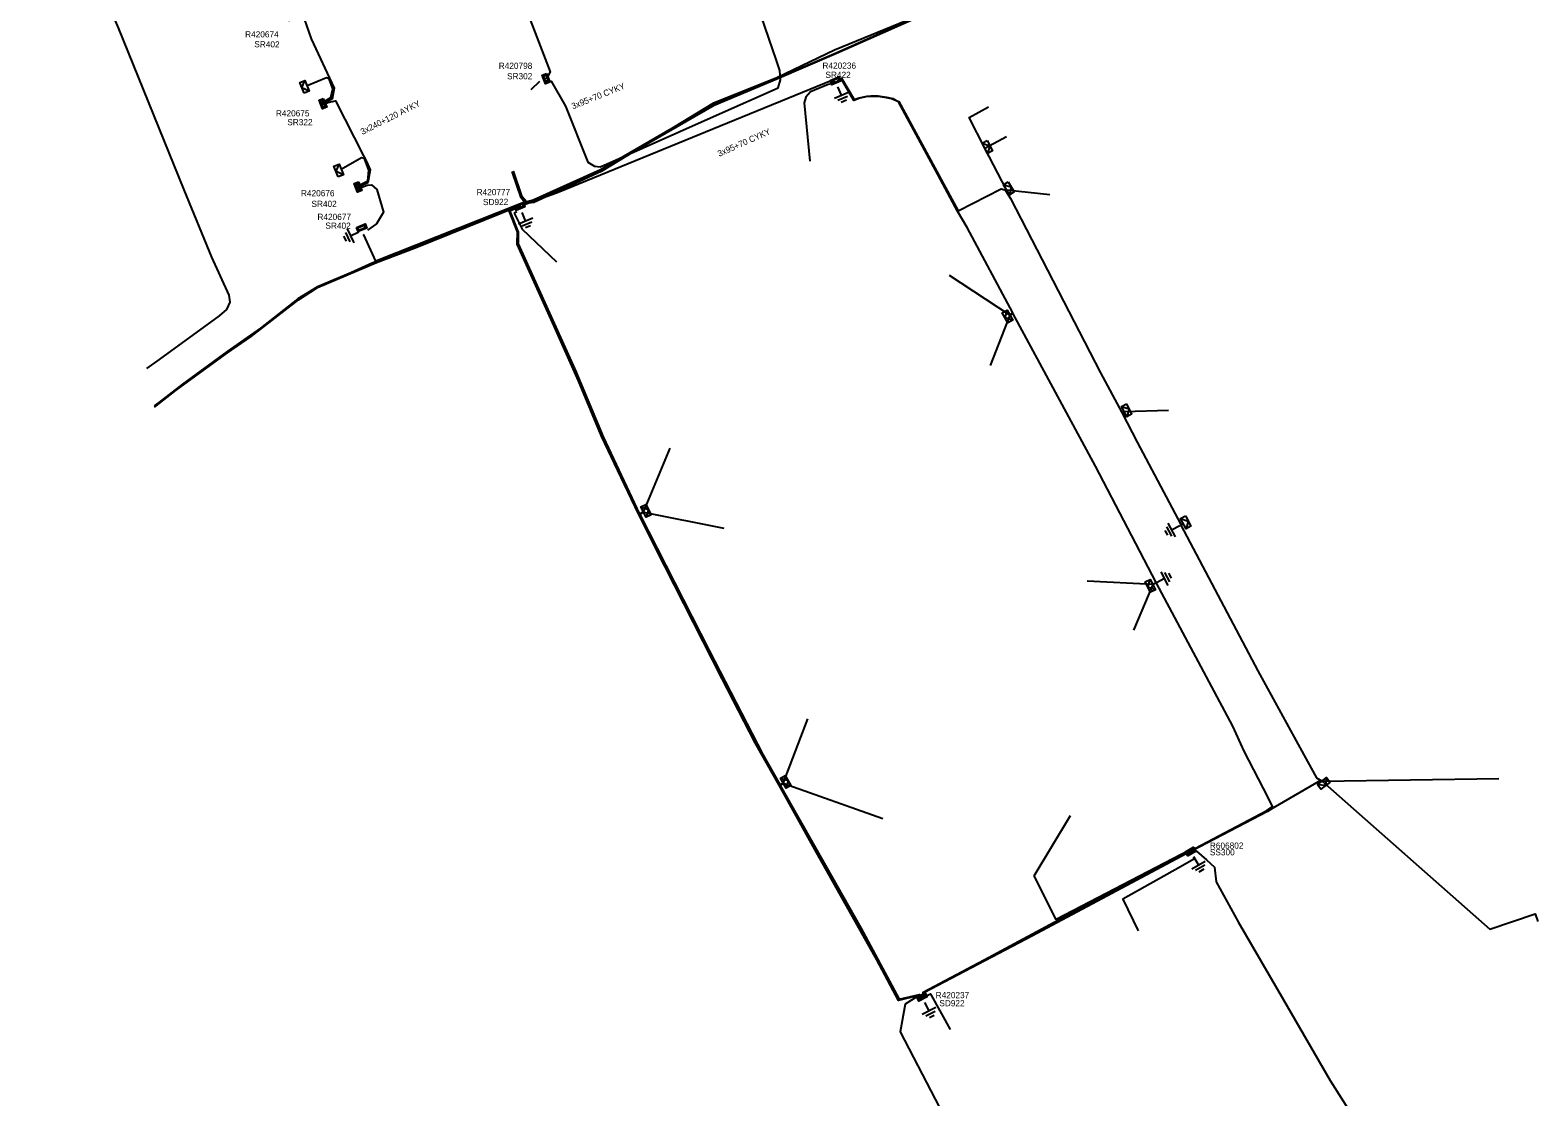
# Model space of a CAD drawing. Extents: x -540028 to -538776, y -1157064 to -1155670.
# Drawn here: x -539936.3 to -539692.4, y -1156587.3 to -1156414.7 of the extents above; entities that cross this region are included whole.
import ezdxf

# ---------------------------------------------------------------- set-up
doc = ezdxf.new("R2010")
doc.units = 0
for name, color, linetype in [('Vrstva 15', 7, 'Continuous'), ('Vrstva 2', 7, 'Continuous'), ('Vrstva 28', 7, 'Continuous'), ('Vrstva 29', 7, 'Continuous'), ('Vrstva 30', 7, 'Continuous'), ('Vrstva 31', 7, 'Continuous'), ('Vrstva 5', 7, 'Continuous'), ('Vrstva 52', 7, 'Continuous'), ('Vrstva 59', 7, 'Continuous'), ('Vrstva 6', 7, 'Continuous'), ('Vrstva 9', 7, 'Continuous')]:
    doc.layers.add(name, color=color, linetype=linetype)

# ---------------------------------------------------------------- blocks, each defined once
blk = doc.blocks.new('132')
at = {"layer": 'Vrstva 2'}
for points in [[(-1.5, 1.5), (1.5, 1.5), (1.5, 0), (-1.5, 0)], [(-1.1, 1.2), (1.1, 1.2), (1.1, 0.3), (-1.1, 0.3)]]:
    blk.add_lwpolyline(points, close=True, dxfattribs=at)
blk = doc.blocks.new('23')
at = {"layer": 'Vrstva 2'}
blk.add_lwpolyline([(1.875, -1.8), (-1.875, -1.8), (-1.875, 0), (1.875, 0)], close=True, dxfattribs=at)
blk.add_lwpolyline([(1.875, 0), (0, -1.8), (-1.875, 0)], dxfattribs=at)
blk = doc.blocks.new('11')
at = {"layer": 'Vrstva 2'}
for p, q in [((-2.5, -4.3), (2.5, -4.3)), ((0, -4.3), (0, -1.3)), ((-1.7, -5.3), (1.7, -5.3)), ((-0.9, -6.3), (0.9, -6.3))]:
    blk.add_line(p, q, dxfattribs=at)

msp = doc.modelspace()

# ---------------------------------------------------------------- linework, layer by layer
at = {"layer": 'Vrstva 5'}
for points in [[(-539936.27, -1156379.01), (-539935.17, -1156382.16), (-539934, -1156386.11), (-539929.5, -1156397.08), (-539922.06, -1156414.34), (-539911.42, -1156440.51), (-539906.94, -1156451.42), (-539904.12, -1156457.59), (-539903.96, -1156458.69), (-539904.52, -1156459.9), (-539905.72, -1156460.91), (-539915.38, -1156467.98), (-539917.46, -1156469.44)], [(-539859.58, -1156406.32), (-539858.22, -1156406.28), (-539857.01, -1156408.79), (-539852.18, -1156421.45), (-539852.7, -1156422.48), (-539853.18, -1156422.63)], [(-539853.12, -1156422.78), (-539851.98, -1156422.96), (-539849.68, -1156426.99), (-539846.07, -1156436.04), (-539845, -1156436.69), (-539844.1, -1156436.81), (-539843.07, -1156436.4), (-539825.27, -1156428.44), (-539815.27, -1156424.04), (-539814.92, -1156422.74), (-539815.01, -1156421.21), (-539815.55, -1156419.63), (-539818.05, -1156412.39), (-539819.4, -1156409.99), (-539820.22, -1156409.98)], [(-539894.46, -1156413.12), (-539892.8, -1156412.5), (-539891.93, -1156412.88), (-539890.82, -1156416.13), (-539887.09, -1156424.1), (-539887.44, -1156425.89), (-539889.25, -1156426.75)], [(-539856.53, -1156443.37), (-539856.4, -1156443.15), (-539856.06, -1156442.79), (-539850.85, -1156440.93), (-539824.69, -1156430.16), (-539806.6, -1156422.79), (-539806, -1156423.17), (-539805.95, -1156423.26)], [(-539805.74, -1156423.17), (-539805.69, -1156422.96), (-539805.02, -1156422.49), (-539803.02, -1156425.91), (-539802.21, -1156425.64), (-539800.91, -1156425.38), (-539800.3, -1156425.33), (-539799.1, -1156425.34), (-539797.76, -1156425.55), (-539796.73, -1156425.76), (-539796.2, -1156426.07), (-539795.78, -1156426.27), (-539786.16, -1156443.91), (-539779.24, -1156440.38), (-539778.6, -1156440.54), (-539778.37, -1156440.53), (-539778.52, -1156440.66), (-539777.73, -1156441.94), (-539763.15, -1156470.16), (-539759.7, -1156476.58), (-539759.34, -1156476.4), (-539759.67, -1156476.64), (-539757.2, -1156481.36), (-539750.18, -1156494.7), (-539749.75, -1156494.55), (-539750.14, -1156494.79), (-539737.72, -1156518.36), (-539730.28, -1156531.93), (-539728.22, -1156535.68), (-539727.31, -1156536.21), (-539727.55, -1156536.12), (-539735.28, -1156540.57), (-539736.14, -1156541.1), (-539748.33, -1156547.45), (-539748.24, -1156547.83)], [(-539791.79, -1156571.37), (-539791.86, -1156570.33), (-539781.96, -1156565.08), (-539767.14, -1156557.14), (-539752.67, -1156549.61), (-539736.27, -1156540.97), (-539735.34, -1156540.31), (-539736.02, -1156538.84), (-539739.94, -1156531.35), (-539741.74, -1156527.33), (-539754.09, -1156504.16), (-539754.7, -1156504.4), (-539754.14, -1156504.06), (-539763.97, -1156485.26), (-539777.26, -1156460.59), (-539777.8, -1156460.81), (-539777.33, -1156460.43), (-539784.72, -1156446.61), (-539786.3, -1156443.97), (-539789.85, -1156437.38), (-539794.36, -1156429), (-539795.84, -1156426.31), (-539796.94, -1156425.84), (-539797.76, -1156425.63), (-539799.14, -1156425.42), (-539800.84, -1156425.45), (-539802.08, -1156425.68), (-539803.03, -1156426.06), (-539805.04, -1156422.63), (-539805.54, -1156422.96), (-539805.61, -1156423.11)], [(-539889.2, -1156426.87), (-539888.1, -1156426.41), (-539886.87, -1156426.13), (-539882.38, -1156435.02), (-539881.91, -1156435.82), (-539881.26, -1156437.29), (-539881.67, -1156439.42), (-539883.56, -1156440.2)], [(-539883.48, -1156440.42), (-539881.79, -1156439.78), (-539881.05, -1156439.75), (-539880.22, -1156440.5), (-539879.12, -1156444.15), (-539880.26, -1156446.06), (-539881.69, -1156447.08)], [(-539856.95, -1156443.54), (-539857.16, -1156442.98), (-539863.41, -1156445.53), (-539871.86, -1156448.88), (-539880.84, -1156452.37), (-539884.41, -1156453.94), (-539889.79, -1156456.24), (-539892.98, -1156458.18), (-539899.04, -1156462.94), (-539904.4, -1156466.7), (-539911.65, -1156471.98), (-539915.48, -1156474.93), (-539916.2, -1156475.5)], [(-539916.17, -1156475.67), (-539912.65, -1156472.92), (-539904.33, -1156466.89), (-539900.54, -1156464.28), (-539892.89, -1156458.34), (-539889.79, -1156456.35), (-539880.25, -1156452.31), (-539874.02, -1156449.93), (-539857.19, -1156443.11), (-539857.03, -1156443.58)], [(-539856.85, -1156443.5), (-539857.14, -1156442.86), (-539880.36, -1156452.08), (-539882.31, -1156447.81), (-539882.33, -1156447.78)], [(-539792.02, -1156571.49), (-539792.4, -1156570.93), (-539792.53, -1156570.86), (-539795.81, -1156571.69), (-539799.35, -1156565.12), (-539809.38, -1156547.23), (-539815.14, -1156536.84), (-539818.99, -1156530.02), (-539824.32, -1156519.66), (-539833.62, -1156501.41), (-539837.9, -1156492.97), (-539840.7, -1156487.1), (-539843.85, -1156480.39), (-539847.57, -1156471.45), (-539851.53, -1156462.61), (-539857.51, -1156449.31), (-539857.46, -1156447.33), (-539858.82, -1156443.93), (-539857.25, -1156443.3), (-539857.13, -1156443.62)], [(-539857.28, -1156443.69), (-539857.38, -1156443.42), (-539858.68, -1156443.96), (-539857.32, -1156447.39), (-539857.36, -1156449.28), (-539847.96, -1156470.03), (-539847.34, -1156471.51), (-539847.3, -1156471.56), (-539847.29, -1156471.62), (-539843.59, -1156480.47), (-539837.72, -1156493), (-539837.11, -1156492.65), (-539837.08, -1156492.66), (-539837.09, -1156492.69), (-539837.68, -1156493.07), (-539826.45, -1156515.06), (-539817.77, -1156531.87), (-539815.02, -1156536.74), (-539814.5, -1156536.53), (-539814.46, -1156536.53), (-539814.47, -1156536.57), (-539814.95, -1156536.88), (-539801.93, -1156559.95), (-539795.74, -1156571.49), (-539792.41, -1156570.69), (-539791.89, -1156571.42)], [(-539748.37, -1156547.9), (-539748.47, -1156547.52), (-539774.14, -1156561.21), (-539791.71, -1156570.45), (-539791.61, -1156571.28)], [(-539748.12, -1156547.76), (-539748.15, -1156547.64), (-539747.65, -1156547.52), (-539745.99, -1156548.95), (-539744.7, -1156550.09), (-539744.42, -1156552.47), (-539740.91, -1156558.97), (-539733.54, -1156571.6), (-539725.99, -1156584.61), (-539720.28, -1156593.61), (-539715.52, -1156601.29), (-539710.21, -1156609.42), (-539702.18, -1156621.59), (-539698.05, -1156627.79), (-539696.4, -1156629.22), (-539694.94, -1156629.28), (-539693.3, -1156628.56)], [(-539792.14, -1156571.55), (-539792.67, -1156570.98), (-539794.72, -1156572.28), (-539795.56, -1156576.77), (-539787.72, -1156591.78), (-539774.46, -1156616.16), (-539774.26, -1156616.09), (-539774.39, -1156616.27), (-539759.6, -1156641.25), (-539756.91, -1156637.89), (-539753.73, -1156636.27), (-539753.42, -1156636.82)]]:
    msp.add_lwpolyline(points, dxfattribs=at)
at = {"layer": 'Vrstva 52'}
for points in [[(-539889.3, -1156426.62), (-539887.62, -1156425.59), (-539887.32, -1156424.19), (-539887.89, -1156422.6), (-539888.34, -1156422.41), (-539891.47, -1156423.71)], [(-539806.36, -1156423.46), (-539806.73, -1156423.39), (-539807.18, -1156423.49), (-539810.06, -1156424.69), (-539810.83, -1156425.52), (-539811.06, -1156426.46), (-539810.17, -1156435.9)], [(-539883.62, -1156440.06), (-539881.66, -1156439.1), (-539881.51, -1156437.34), (-539882.2, -1156435.44), (-539882.68, -1156435.35), (-539885.96, -1156437.24)], [(-539778.37, -1156440.53), (-539781.86, -1156433.82)], [(-539857.57, -1156444.11), (-539857.96, -1156444.3)], [(-539748.5, -1156547.98), (-539748.59, -1156547.64), (-539748.74, -1156547.34), (-539770.34, -1156558.58), (-539773.87, -1156551.5)], [(-539748.12, -1156548.56), (-539748.03, -1156548.8), (-539750.22, -1156550.06)], [(-539791.45, -1156571.24), (-539791.47, -1156570.98), (-539790.66, -1156570.63), (-539790.55, -1156570.81)]]:
    msp.add_lwpolyline(points, dxfattribs=at)
at = {"layer": 'Vrstva 59'}
for points in [[(-539853.88, -1156423), (-539855.29, -1156424.35)], [(-539781.86, -1156433.82), (-539784.41, -1156428.81), (-539781.24, -1156427.11)], [(-539781.86, -1156433.82), (-539778.38, -1156431.92)], [(-539778.37, -1156440.53), (-539771.37, -1156441.29)], [(-539857.96, -1156444.3), (-539856.7, -1156446.92), (-539851.13, -1156452.17)], [(-539777.8, -1156460.81), (-539787.59, -1156454.38)], [(-539777.8, -1156460.81), (-539780.98, -1156468.93)], [(-539759.34, -1156476.4), (-539752.16, -1156476.2)], [(-539837.08, -1156492.66), (-539832.75, -1156482.35)], [(-539837.08, -1156492.66), (-539824.06, -1156495.26)], [(-539754.7, -1156504.4), (-539765.31, -1156503.83)], [(-539754.7, -1156504.4), (-539757.81, -1156511.77)], [(-539814.47, -1156536.57), (-539810.5, -1156526.09)], [(-539727.31, -1156536.21), (-539698.74, -1156535.76)], [(-539814.46, -1156536.53), (-539798.36, -1156542.25)], [(-539727.31, -1156536.21), (-539700.16, -1156560.12), (-539692.85, -1156557.68), (-539692.41, -1156558.92)], [(-539773.87, -1156551.5), (-539768.02, -1156541.75)], [(-539750.22, -1156550.06), (-539759.54, -1156555.29), (-539757.04, -1156560.42)], [(-539790.55, -1156570.81), (-539787.49, -1156576.37)]]:
    msp.add_lwpolyline(points, dxfattribs=at)
at = {"layer": 'Vrstva 9'}
for points in [[(-539759.51, -1156398.14), (-539759.62, -1156398.62), (-539760.06, -1156399), (-539761.6, -1156399.81), (-539769.45, -1156403.8), (-539779.17, -1156407.25), (-539782.36, -1156408.57), (-539793.3, -1156412.95), (-539805.86, -1156418.48), (-539815.48, -1156422.64), (-539825.64, -1156426.87), (-539843.97, -1156437.46), (-539854.84, -1156442.49), (-539856.09, -1156442.63), (-539856.77, -1156441.76), (-539858.17, -1156437.54)], [(-539759.76, -1156398.24), (-539759.77, -1156398.65), (-539760.65, -1156399.26), (-539761.61, -1156399.69), (-539769.4, -1156403.69), (-539779.21, -1156407.2), (-539782.34, -1156408.48), (-539793.32, -1156412.83), (-539805.9, -1156418.42), (-539815.47, -1156422.51), (-539825.7, -1156426.67), (-539844.05, -1156437.32), (-539854.91, -1156442.23), (-539855.97, -1156442.49), (-539856.71, -1156441.67), (-539858.08, -1156437.54)], [(-539793.39, -1156412.7), (-539806.19, -1156417.96), (-539815.52, -1156422.44), (-539825.74, -1156426.52), (-539843.91, -1156437.59), (-539854.78, -1156442.6), (-539856.18, -1156442.74), (-539856.84, -1156441.82), (-539858.29, -1156437.56)]]:
    msp.add_lwpolyline(points, dxfattribs=at)

# ---------------------------------------------------------------- block references
at = {"layer": 'Vrstva 15'}
for p, xscale, yscale, rotation in [((-539805.89, -1156423.26), 0.5, 0.5, 23.00000008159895), ((-539856.97, -1156443.58), 0.49999999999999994, 0.5, 23.000000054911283), ((-539882.54, -1156447.03), 0.5, 0.5, -63.928813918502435), ((-539749.75, -1156494.55), 0.5, 0.5000000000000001, -61.99999998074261), ((-539754.7, -1156504.4), 0.5, 0.5, 117.00000006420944), ((-539748.37, -1156547.9), 0.5, 0.5, 30.256452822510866), ((-539791.86, -1156571.43), 0.49999999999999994, 0.5, 27.000000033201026)]:
    msp.add_blockref('11', p, dxfattribs=dict(at, xscale=xscale, yscale=yscale, rotation=rotation))
at = {"layer": 'Vrstva 28'}
for p, xscale, yscale, rotation in [((-539853.18, -1156422.69), 0.5, 0.5, -68.5049083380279), ((-539805.89, -1156423.26), 0.5000000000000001, 0.5, 22.999999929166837), ((-539889.28, -1156426.74), 0.5, 0.49999999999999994, -68.6991000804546), ((-539883.58, -1156440.23), 0.5, 0.5, -68.6991000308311), ((-539856.97, -1156443.58), 0.5, 0.5, 23.00000008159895), ((-539882.54, -1156447.03), 0.5000000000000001, 0.5, 21.2311139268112), ((-539748.37, -1156547.9), 0.5, 0.5, 30.256452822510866), ((-539791.86, -1156571.43), 0.49999999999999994, 0.5, 27.000000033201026)]:
    msp.add_blockref('132', p, dxfattribs=dict(at, xscale=xscale, yscale=yscale, rotation=rotation))
at = {"layer": 'Vrstva 31'}
for p, xscale, yscale, rotation in [((-539891.48, -1156423.71), 0.49999999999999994, 0.5000000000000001, -67.81543891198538), ((-539781.86, -1156433.82), 0.5, 0.5, 117.71850281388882), ((-539885.96, -1156437.23), 0.49999999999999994, 0.5000000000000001, -67.81543891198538), ((-539778.37, -1156440.53), 0.5, 0.5, 122.00000001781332), ((-539777.8, -1156460.81), 0.5, 0.5, -61.00000001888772), ((-539759.34, -1156476.4), 0.5, 0.5, 117.00000000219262), ((-539837.08, -1156492.66), 0.5, 0.5, 117.00000000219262), ((-539749.75, -1156494.55), 0.5000000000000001, 0.5, 118.00000001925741), ((-539754.7, -1156504.4), 0.5, 0.5, -62.99999993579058), ((-539814.46, -1156536.53), 0.5, 0.49999999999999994, 119.99999996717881), ((-539727.31, -1156536.21), 0.5000000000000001, 0.5, 38.000000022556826)]:
    msp.add_blockref('23', p, dxfattribs=dict(at, xscale=xscale, yscale=yscale, rotation=rotation))

# ---------------------------------------------------------------- texts
at = {"layer": 'Vrstva 29'}
for s, p in [('R420674', (-539901.5, -1156415.88)), ('R420798', (-539860.48, -1156420.97)), ('R420236', (-539808.12, -1156420.94)), ('R420675', (-539896.52, -1156428.65)), ('R420676', (-539892.47, -1156441.58)), ('R420777', (-539864.06, -1156441.4)), ('R420677', (-539889.8, -1156445.41)), ('R606802', (-539745.46, -1156547.13)), ('R420237', (-539789.81, -1156571.31))]:
    msp.add_text(s, height=1, dxfattribs=at).set_placement(p)
at = {"layer": 'Vrstva 30'}
for s, rotation, p in [('SR402', 359.473, (-539900.02, -1156417.47)), ('SR422', 359.956, (-539807.64, -1156422.43)), ('SR302', 0.215, (-539859.14, -1156422.66)), ('SR322', 0.018, (-539894.68, -1156430.09)), ('SR402', 0.234, (-539890.77, -1156443.31)), ('SD922', 0.441, (-539863.03, -1156443.01)), ('SR402', 359.943, (-539888.51, -1156446.83)), ('SD922', 359.958, (-539789.22, -1156572.62))]:
    msp.add_text(s, height=1, rotation=rotation, dxfattribs=at).set_placement(p)
msp.add_text('SS300', height=1, dxfattribs=at).set_placement((-539745.46, -1156548.2))
at = {"layer": 'Vrstva 6'}
for s, rotation, p in [('3x95+70 CYKY', 21.745, (-539848.48, -1156427.52)), ('3x240+120 AYKY', 26.789, (-539882.52, -1156431.66)), ('3x95+70 CYKY', 24.076, (-539824.81, -1156435.2))]:
    msp.add_text(s, height=1, rotation=rotation, dxfattribs=at).set_placement(p)

doc.saveas('drawing.dxf')
